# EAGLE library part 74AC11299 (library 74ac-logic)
8-bit universal SHIFT/STORAGE REGISTER
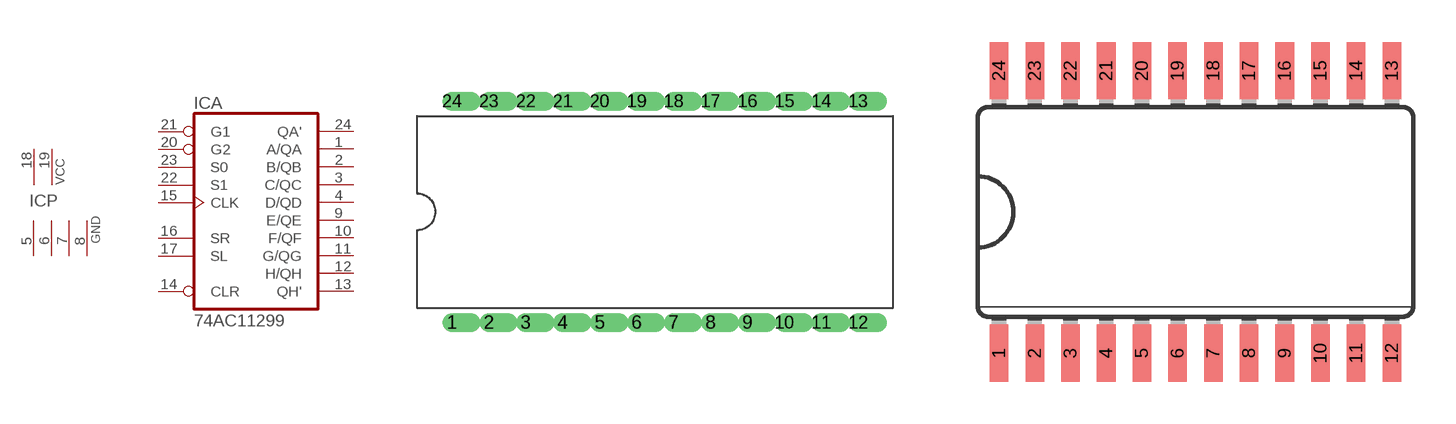
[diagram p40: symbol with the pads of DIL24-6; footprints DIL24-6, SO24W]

Designator prefix IC; gates A=7411299 P=2PWR4GND

## 74AC11299  [DIL24-6]
1  A:A/QA
2  A:B/QB
3  A:C/QC
4  A:D/QD
5  P:GND  pwr
6  P:GND  pwr
7  P:GND  pwr
8  P:GND  pwr
9  A:E/QE
10  A:F/QF
11  A:G/QG
12  A:H/QH
13  A:QH'  out
14  A:CLR  in
15  A:CLK  in
16  A:SR  in
17  A:SL  in
18  P:VCC  pwr
19  P:VCC  pwr
20  A:G2  in
21  A:G1  in
22  A:S1  in
23  A:S0  in
24  A:QA'  out

## 74AC11299D  [SO24W]
Pads as for DIL24-6

## Footprint DIL24-6 (pad centres in mm)
Dual In Line 0.6 inch
drill 0.813 offset: 1 -13.97,-7.62; 2 -11.43,-7.62; 3 -8.89,-7.62; 4 -6.35,-7.62; 5 -3.81,-7.62; 6 -1.27,-7.62; 7 1.27,-7.62; 8 3.81,-7.62; 9 6.35,-7.62; 10 8.89,-7.62; 11 11.43,-7.62; 12 13.97,-7.62; 13 13.97,7.62; 14 11.43,7.62; 15 8.89,7.62; 16 6.35,7.62; 17 3.81,7.62; 18 1.27,7.62; 19 -1.27,7.62; 20 -3.81,7.62; 21 -6.35,7.62; 22 -8.89,7.62; 23 -11.43,7.62; 24 -13.97,7.62

## Footprint SO24W (pad centres in mm)
Wide Small Outline package 300 mil
smd 0.66 x 2.032: 1 -6.985,-5.029; 2 -5.715,-5.029; 3 -4.445,-5.029; 4 -3.175,-5.029; 5 -1.905,-5.029; 6 -0.635,-5.029; 7 0.635,-5.029; 8 1.905,-5.029; 9 3.175,-5.029; 10 4.445,-5.029; 11 5.715,-5.029; 12 6.985,-5.029; 13 6.985,5.029; 14 5.715,5.029; 15 4.445,5.029; 16 3.175,5.029; 17 1.905,5.029; 18 0.635,5.029; 19 -0.635,5.029; 20 -1.905,5.029; 21 -3.175,5.029; 22 -4.445,5.029; 23 -5.715,5.029; 24 -6.985,5.029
